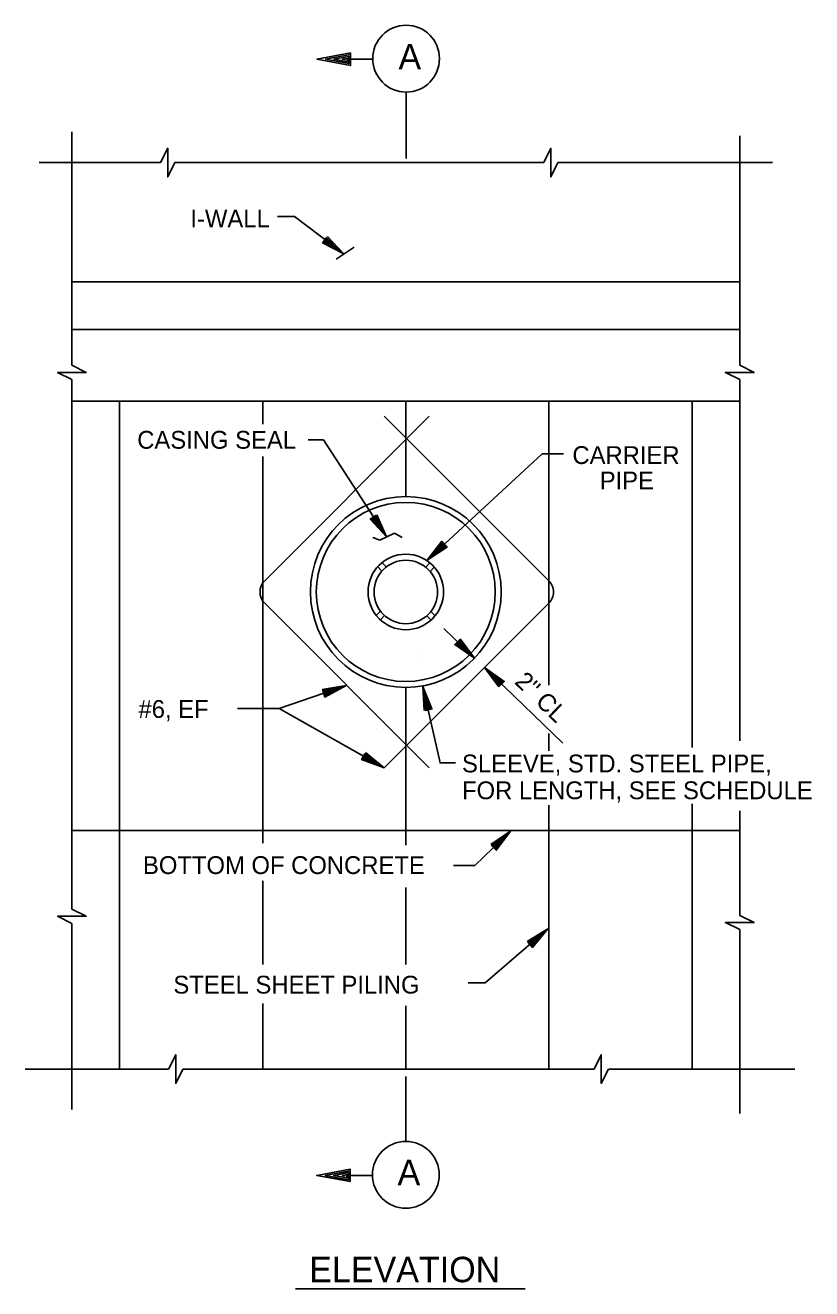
# Model space of a CAD drawing. Extents: x 22411.4 to 22495.4, y 22369.6 to 22415.
# Drawn here: x 22413.3 to 22421.55, y 22401.71 to 22414.95 of the extents above; entities that cross this region are included whole.
import ezdxf

# ---------------------------------------------------------------- set-up
doc = ezdxf.new("R2010")
doc.units = 0
for name, color, linetype in [('Level 1', 7, 'Continuous'), ('Level 10', 7, 'Continuous'), ('Level 2', 7, 'Continuous'), ('Level 3', 7, 'Continuous'), ('Level 4', 7, 'Continuous'), ('Level 8', 7, 'Continuous')]:
    doc.layers.add(name, color=color, linetype=linetype)

msp = doc.modelspace()

# ---------------------------------------------------------------- linework, layer by layer
at = {"layer": 'Level 1'}
for p, q in [((22413.791, 22411.386), (22413.791, 22413.831)), ((22420.791, 22411.386), (22420.791, 22413.79)), ((22413.448, 22413.51), (22414.721, 22413.51)), ((22414.87, 22413.51), (22418.736, 22413.51)), ((22418.886, 22413.51), (22421.134, 22413.51)), ((22416.56, 22412.497), (22416.749, 22412.624)), ((22416.587, 22412.594), (22416.587, 22412.594)), ((22416.642, 22412.552), (22416.642, 22412.552)), ((22413.791, 22405.687), (22413.791, 22411.237)), ((22420.791, 22407.45), (22420.791, 22411.237)), ((22413.791, 22411.01), (22420.791, 22411.01)), ((22414.291, 22406.51), (22414.291, 22411.01)), ((22415.791, 22410.767), (22415.791, 22411.01)), ((22417.291, 22410.01), (22417.291, 22411.01)), ((22418.791, 22411.01), (22418.791, 22408.033)), ((22420.291, 22407.379), (22420.291, 22411.01)), ((22415.791, 22406.51), (22415.791, 22410.428)), ((22417.017, 22409.552), (22417.171, 22409.625)), ((22417.051, 22409.646), (22417.051, 22409.646)), ((22417.171, 22409.625), (22417.252, 22409.579)), ((22417.017, 22409.552), (22416.947, 22409.581)), ((22417.088, 22409.588), (22417.088, 22409.588)), ((22417.566, 22409.39), (22417.566, 22409.39)), ((22417.04, 22409.229), (22416.996, 22409.274)), ((22417.085, 22409.272), (22417.041, 22409.317)), ((22417.5, 22409.27), (22417.544, 22409.314)), ((22417.515, 22409.343), (22417.515, 22409.343)), ((22417.545, 22409.226), (22417.589, 22409.271)), ((22416.981, 22408.764), (22417.026, 22408.808)), ((22417.024, 22408.718), (22417.068, 22408.762)), ((22417.555, 22408.715), (22417.51, 22408.759)), ((22417.598, 22408.76), (22417.553, 22408.804)), ((22417.688, 22408.628), (22418.011, 22408.316)), ((22417.752, 22408.566), (22417.752, 22408.566)), ((22417.802, 22408.518), (22417.802, 22408.518)), ((22417.463, 22408.356), (22417.463, 22408.356)), ((22417.926, 22408.399), (22417.926, 22408.399)), ((22417.976, 22408.35), (22417.976, 22408.35)), ((22416.75, 22408.192), (22416.75, 22408.192)), ((22416.808, 22408.23), (22416.808, 22408.23)), ((22417.463, 22408.286), (22417.463, 22408.286)), ((22418.114, 22408.217), (22418.936, 22407.425)), ((22417.291, 22406.51), (22417.291, 22408.01)), ((22416.986, 22407.581), (22416.986, 22407.581)), ((22417.053, 22407.564), (22417.053, 22407.564)), ((22418.791, 22407.344), (22418.791, 22407.527)), ((22418.791, 22406.51), (22418.791, 22406.776)), ((22420.291, 22406.51), (22420.291, 22406.79)), ((22420.791, 22405.62), (22420.791, 22406.717)), ((22418.34, 22406.457), (22418.34, 22406.457)), ((22418.39, 22406.505), (22418.39, 22406.505)), ((22413.791, 22403.587), (22413.791, 22405.537)), ((22418.728, 22405.433), (22418.728, 22405.433)), ((22418.78, 22405.478), (22418.78, 22405.478)), ((22420.791, 22403.544), (22420.791, 22405.471)), ((22413.302, 22404.01), (22414.804, 22404.01)), ((22414.954, 22404.01), (22419.266, 22404.01)), ((22419.415, 22404.01), (22421.368, 22404.01))]:
    msp.add_line(p, q, dxfattribs=at)
for points in [[(22414.721, 22413.51), (22414.795, 22413.66), (22414.795, 22413.36), (22414.87, 22413.51)], [(22418.736, 22413.51), (22418.811, 22413.66), (22418.811, 22413.36), (22418.886, 22413.51)], [(22413.791, 22411.237), (22413.641, 22411.311), (22413.941, 22411.311), (22413.791, 22411.386)], [(22420.791, 22411.237), (22420.641, 22411.311), (22420.941, 22411.311), (22420.791, 22411.386)], [(22417.86, 22408.519), (22418.011, 22408.316), (22417.803, 22408.459), (22417.852, 22408.51), (22417.961, 22408.364), (22417.82, 22408.462), (22417.851, 22408.494), (22417.913, 22408.411), (22417.837, 22408.464), (22417.85, 22408.477), (22417.863, 22408.459)], [(22418.265, 22408.014), (22418.114, 22408.217), (22418.323, 22408.073), (22418.274, 22408.022), (22418.164, 22408.169), (22418.306, 22408.071), (22418.274, 22408.039), (22418.212, 22408.122), (22418.289, 22408.069), (22418.276, 22408.056), (22418.262, 22408.074)], [(22413.791, 22405.537), (22413.641, 22405.612), (22413.941, 22405.612), (22413.791, 22405.687)], [(22420.791, 22405.471), (22420.641, 22405.545), (22420.941, 22405.545), (22420.791, 22405.62)], [(22414.804, 22404.01), (22414.879, 22404.16), (22414.879, 22403.86), (22414.954, 22404.01)], [(22419.266, 22404.01), (22419.34, 22404.16), (22419.34, 22403.86), (22419.415, 22404.01)]]:
    msp.add_lwpolyline(points, dxfattribs=at)
at = {"layer": 'Level 10'}
for p, q in [((22417.537, 22410.853), (22415.813, 22409.128)), ((22418.79, 22409.128), (22417.065, 22410.853)), ((22417.537, 22407.167), (22415.813, 22408.892)), ((22418.79, 22408.892), (22417.065, 22407.167)), ((22416.136, 22401.708), (22418.543, 22401.708))]:
    msp.add_line(p, q, dxfattribs=at)
for centre, start, end in [((22415.93, 22409.01), 135, 225), ((22418.672, 22409.01), 314.9998, 45.0002)]:
    msp.add_arc(centre, 0.167, start, end, dxfattribs=at)
at = {"layer": 'Level 2'}
for p, q in [((22415.946, 22412.945), (22416.125, 22412.945)), ((22416.125, 22412.945), (22416.642, 22412.552)), ((22413.791, 22412.26), (22420.791, 22412.26)), ((22413.791, 22411.76), (22420.791, 22411.76)), ((22416.267, 22410.606), (22416.428, 22410.606)), ((22416.428, 22410.606), (22417.088, 22409.588)), ((22418.72, 22410.456), (22417.515, 22409.343)), ((22418.72, 22410.456), (22418.944, 22410.456)), ((22415.964, 22407.789), (22416.666, 22408.029)), ((22415.527, 22407.789), (22415.964, 22407.789)), ((22415.964, 22407.789), (22417.065, 22407.167)), ((22413.791, 22406.51), (22420.791, 22406.51)), ((22414.291, 22404.01), (22414.291, 22406.51)), ((22415.791, 22406.376), (22415.791, 22406.51)), ((22417.291, 22406.358), (22417.291, 22406.51)), ((22418.016, 22406.145), (22418.39, 22406.505)), ((22418.791, 22404.01), (22418.791, 22406.51)), ((22420.291, 22404.01), (22420.291, 22406.51)), ((22417.79, 22406.145), (22418.016, 22406.145)), ((22415.791, 22405.105), (22415.791, 22405.983)), ((22417.291, 22405.105), (22417.291, 22405.912)), ((22418.124, 22404.912), (22418.78, 22405.478)), ((22417.945, 22404.912), (22418.124, 22404.912)), ((22415.791, 22404.01), (22415.791, 22404.697)), ((22417.291, 22404.01), (22417.291, 22404.672))]:
    msp.add_line(p, q, dxfattribs=at)
for points in [[(22416.469, 22412.736), (22416.642, 22412.552), (22416.419, 22412.67), (22416.461, 22412.726), (22416.587, 22412.594), (22416.435, 22412.674), (22416.463, 22412.71), (22416.534, 22412.634), (22416.452, 22412.678), (22416.463, 22412.693), (22416.479, 22412.676)], [(22416.987, 22409.819), (22417.088, 22409.588), (22416.918, 22409.774), (22416.977, 22409.813), (22417.051, 22409.646), (22416.935, 22409.773), (22416.973, 22409.797), (22417.014, 22409.702), (22416.952, 22409.771), (22416.968, 22409.781), (22416.977, 22409.76)], [(22417.727, 22409.482), (22417.515, 22409.343), (22417.67, 22409.542), (22417.718, 22409.49), (22417.566, 22409.39), (22417.672, 22409.525), (22417.702, 22409.492), (22417.615, 22409.435), (22417.673, 22409.508), (22417.686, 22409.495), (22417.666, 22409.482)], [(22416.416, 22407.987), (22416.666, 22408.029), (22416.443, 22407.909), (22416.42, 22407.976), (22416.6, 22408.007), (22416.449, 22407.925), (22416.434, 22407.968), (22416.537, 22407.985), (22416.455, 22407.941), (22416.449, 22407.959), (22416.471, 22407.963)], [(22417.812, 22407.218), (22417.65, 22407.218), (22417.47, 22408.019)], [(22417.484, 22407.766), (22417.47, 22408.019), (22417.565, 22407.784), (22417.496, 22407.769), (22417.485, 22407.951), (22417.55, 22407.792), (22417.505, 22407.782), (22417.5, 22407.886), (22417.534, 22407.799), (22417.516, 22407.795), (22417.515, 22407.818)], [(22416.868, 22407.326), (22417.065, 22407.167), (22416.828, 22407.254), (22416.862, 22407.315), (22417.005, 22407.201), (22416.844, 22407.26), (22416.866, 22407.3), (22416.947, 22407.234), (22416.859, 22407.267), (22416.869, 22407.283), (22416.886, 22407.268)], [(22418.182, 22406.362), (22418.39, 22406.505), (22418.239, 22406.303), (22418.19, 22406.354), (22418.34, 22406.457), (22418.238, 22406.32), (22418.206, 22406.352), (22418.292, 22406.411), (22418.236, 22406.337), (22418.223, 22406.35), (22418.242, 22406.363)], [(22418.564, 22405.346), (22418.78, 22405.478), (22418.618, 22405.284), (22418.572, 22405.337), (22418.728, 22405.433), (22418.618, 22405.301), (22418.588, 22405.335), (22418.677, 22405.389), (22418.617, 22405.318), (22418.605, 22405.332), (22418.625, 22405.344)]]:
    msp.add_lwpolyline(points, dxfattribs=at)
for radius in [1, 0.938, 0.396, 0.333]:
    msp.add_circle((22417.291, 22409.01), radius, dxfattribs=at)
at = {"layer": 'Level 3'}
for p, q in [((22416.71, 22414.592), (22416.944, 22414.592)), ((22417.294, 22413.554), (22417.294, 22414.243)), ((22417.291, 22403.933), (22417.291, 22403.245)), ((22416.707, 22402.895), (22416.941, 22402.895))]:
    msp.add_line(p, q, dxfattribs=at)
for points in [[(22416.71, 22414.641), (22416.71, 22414.659), (22416.36, 22414.592), (22416.71, 22414.527), (22416.71, 22414.641), (22416.45, 22414.593), (22416.693, 22414.547), (22416.693, 22414.622), (22416.538, 22414.593), (22416.677, 22414.567), (22416.677, 22414.602), (22416.627, 22414.593), (22416.66, 22414.587)], [(22416.707, 22402.944), (22416.707, 22402.962), (22416.357, 22402.895), (22416.707, 22402.83), (22416.707, 22402.944), (22416.447, 22402.896), (22416.69, 22402.85), (22416.69, 22402.925), (22416.535, 22402.896), (22416.674, 22402.87), (22416.674, 22402.905), (22416.624, 22402.896), (22416.657, 22402.89)]]:
    msp.add_lwpolyline(points, dxfattribs=at)
for centre in [(22417.294, 22414.599), (22417.291, 22402.902)]:
    msp.add_circle(centre, 0.35, dxfattribs=at)
at = {"layer": 'Level 8'}
for p, q in [((22416.666, 22408.029), (22416.666, 22408.029)), ((22416.6, 22408.007), (22416.6, 22408.007)), ((22417.47, 22408.019), (22417.47, 22408.019)), ((22417.485, 22407.951), (22417.485, 22407.951)), ((22417.005, 22407.201), (22417.005, 22407.201)), ((22417.065, 22407.167), (22417.065, 22407.167))]:
    msp.add_line(p, q, dxfattribs=at)

# ---------------------------------------------------------------- texts
at = {"layer": 'Level 3'}
for s, height, p in [('A', 0.267, (22417.214, 22414.486)), ('A', 0.267, (22417.204, 22402.793)), ('ELEVATION', 0.2667, (22416.279, 22401.776))]:
    msp.add_text(s, height=height, dxfattribs=at).set_placement(p)
at = {"layer": 'Level 4'}
for s, height, p in [('I-WALL', 0.1867, (22415.033, 22412.83)), ('CASING SEAL', 0.18667, (22414.476, 22410.511)), ('CARRIER', 0.1867, (22419.037, 22410.351)), ('PIPE', 0.1867, (22419.323, 22410.085)), ('#6, EF', 0.1867, (22414.489, 22407.69)), ('SLEEVE, STD. STEEL PIPE,', 0.18667, (22417.88, 22407.119)), ('FOR LENGTH, SEE SCHEDULE', 0.18667, (22417.88, 22406.838)), ('BOTTOM OF CONCRETE', 0.18667, (22414.536, 22406.054)), ('STEEL SHEET PILING', 0.18667, (22414.855, 22404.801))]:
    msp.add_text(s, height=height, dxfattribs=at).set_placement(p)
msp.add_text("2'' CL", height=0.1867, rotation=316.0562, dxfattribs=at).set_placement((22418.421, 22408.058))

doc.saveas('drawing.dxf')
